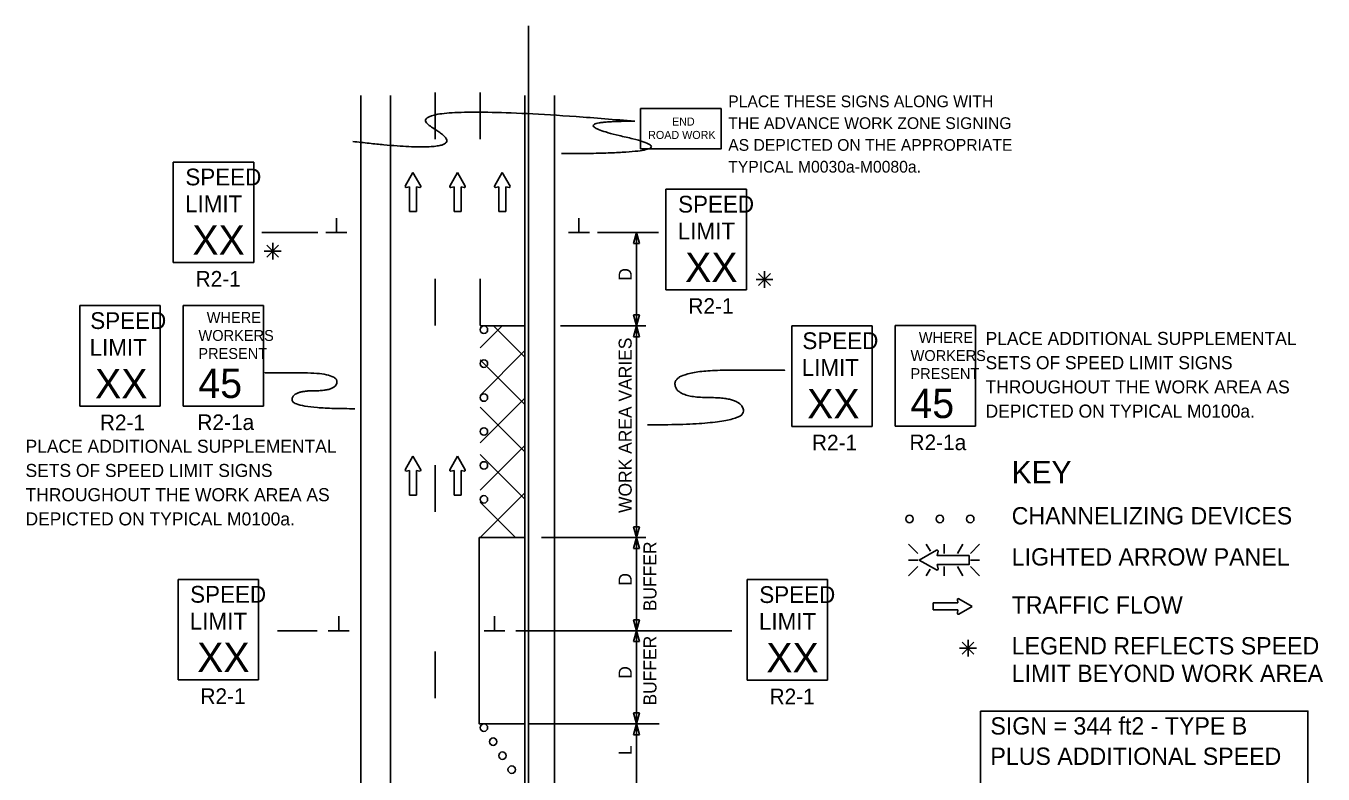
# Model space of a CAD drawing. Extents: x 16733 to 18475, y 5932 to 6964.
# Drawn here: x 16733 to 17429, y 6562 to 6964 of the extents above; entities that cross this region are included whole.
import ezdxf

# ---------------------------------------------------------------- set-up
doc = ezdxf.new("R2010")
doc.units = 0
for name, color, linetype in [('ALI_LEGAL_EX', 7, 'Continuous'), ('MT_SCRATCH_LEVEL_E', 7, 'Continuous'), ('PAVT_EDGE_EX', 7, 'Continuous'), ('TRAFFIC_SIGNS_PR', 7, 'Continuous'), ('TYPICAL_TEXT_DIMEN_EX', 7, 'Continuous'), ('TYPICAL_TEXT_DIMEN_PR', 7, 'Continuous')]:
    doc.layers.add(name, color=color, linetype=linetype)

msp = doc.modelspace()

# ---------------------------------------------------------------- linework, layer by layer
at = {"layer": 'ALI_LEGAL_EX'}
msp.add_line((17002.72, 6964.07), (17002.72, 6147.1), dxfattribs=at)
for points in [[(16952.72, 6928.28), (16952.72, 6903.28)], [(16976.72, 6928.28), (16976.72, 6903.28)], [(16952.72, 6828.28), (16952.72, 6803.28)], [(16976.72, 6828.28), (16976.72, 6803.28)], [(16952.72, 6728.28), (16952.72, 6703.28)], [(16952.72, 6628.28), (16952.72, 6603.28)]]:
    msp.add_lwpolyline(points, dxfattribs=at)
at = {"layer": 'MT_SCRATCH_LEVEL_E'}
for p, q in [((16940.72, 6885.31), (16936.61, 6878.07)), ((16944.87, 6878.07), (16940.72, 6885.31)), ((16964.62, 6885.31), (16960.51, 6878.07)), ((16968.77, 6878.07), (16964.62, 6885.31)), ((16988.68, 6885.31), (16984.56, 6878.07)), ((16992.82, 6878.07), (16988.68, 6885.31)), ((16937.09, 6877.38), (16938.87, 6877.7)), ((16938.87, 6877.7), (16938.87, 6864.44)), ((16942.61, 6864.44), (16942.61, 6877.7)), ((16942.61, 6877.7), (16944.39, 6877.38)), ((16960.99, 6877.38), (16962.77, 6877.7)), ((16962.77, 6877.7), (16962.77, 6864.44)), ((16966.51, 6864.44), (16966.51, 6877.7)), ((16966.51, 6877.7), (16968.29, 6877.38)), ((16985.05, 6877.38), (16986.82, 6877.7)), ((16986.82, 6877.7), (16986.82, 6864.44)), ((16990.57, 6864.44), (16990.57, 6877.7)), ((16990.57, 6877.7), (16992.34, 6877.38)), ((16938.87, 6864.44), (16942.61, 6864.44)), ((16962.77, 6864.44), (16966.51, 6864.44)), ((16986.82, 6864.44), (16990.57, 6864.44)), ((16940.72, 6733.05), (16936.61, 6725.81)), ((16944.87, 6725.81), (16940.72, 6733.05)), ((16964.62, 6733.05), (16960.51, 6725.81)), ((16968.77, 6725.81), (16964.62, 6733.05)), ((16937.09, 6725.13), (16938.87, 6725.44)), ((16938.87, 6725.44), (16938.87, 6712.19)), ((16942.61, 6712.19), (16942.61, 6725.44)), ((16942.61, 6725.44), (16944.39, 6725.13)), ((16960.99, 6725.13), (16962.77, 6725.44)), ((16962.77, 6725.44), (16962.77, 6712.19)), ((16966.51, 6712.19), (16966.51, 6725.44)), ((16966.51, 6725.44), (16968.29, 6725.13)), ((16938.87, 6712.19), (16942.61, 6712.19)), ((16962.77, 6712.19), (16966.51, 6712.19)), ((17233.37, 6654.33), (17220.11, 6654.33)), ((17220.11, 6654.33), (17220.11, 6650.59)), ((17233.05, 6656.11), (17233.37, 6654.33)), ((17240.98, 6652.48), (17233.74, 6656.59)), ((17233.74, 6648.33), (17240.98, 6652.48)), ((17220.11, 6650.59), (17233.37, 6650.59)), ((17233.37, 6650.59), (17233.05, 6648.81))]:
    msp.add_line(p, q, dxfattribs=at)
for centre, start, end in [((16937.02, 6877.84), 150.42484, 279.96381), ((16944.46, 6877.84), 260.03619, 29.77312), ((16960.92, 6877.84), 150.42484, 279.96381), ((16968.36, 6877.84), 260.03619, 29.77312), ((16984.97, 6877.84), 150.42484, 279.96381), ((16992.41, 6877.84), 260.03619, 29.77312), ((16937.02, 6725.59), 150.42484, 279.96381), ((16944.46, 6725.59), 260.03619, 29.77312), ((16960.92, 6725.59), 150.42484, 279.96381), ((16968.36, 6725.59), 260.03619, 29.77312), ((17233.51, 6656.18), 60.42484, 189.96381), ((17233.51, 6648.74), 170.03619, 299.77312)]:
    msp.add_arc(centre, 0.463, start, end, dxfattribs=at)
at = {"layer": 'PAVT_EDGE_EX'}
for p, q in [((16912.72, 6926.76), (16912.72, 6278.89)), ((16928.72, 6926.76), (16928.72, 6278.89)), ((17000.72, 6689.4), (17000.72, 6926.76)), ((17016.72, 6926.76), (17016.72, 6278.89)), ((17000.72, 6803.12), (16976.72, 6803.12)), ((16976.72, 6803.12), (17000.72, 6803.12)), ((16976.72, 6791.22), (16988.62, 6803.12)), ((17000.72, 6786.31), (16983.91, 6803.12)), ((16976.72, 6765.77), (17000.72, 6789.77)), ((17000.72, 6760.86), (16976.72, 6784.86)), ((16976.72, 6740.31), (17000.72, 6764.31)), ((17000.72, 6735.4), (16976.72, 6759.4)), ((16976.72, 6714.86), (17000.72, 6738.86)), ((17000.72, 6709.95), (16976.72, 6733.95)), ((16976.72, 6689.4), (17000.72, 6713.4)), ((16995.81, 6689.4), (16976.72, 6708.49)), ((17000.72, 6689.4), (17000.72, 6278.89))]:
    msp.add_line(p, q, dxfattribs=at)
msp.add_lwpolyline([(17000.72, 6689.4), (16976.34, 6689.4), (16976.34, 6589.4), (17000.72, 6589.4)], close=True, dxfattribs=at)
at = {"layer": 'TRAFFIC_SIGNS_PR'}
for p, q in [((16812.01, 6891.02), (16855.21, 6891.02)), ((16812.01, 6837.02), (16812.01, 6891.02)), ((16855.21, 6837.02), (16855.21, 6891.02)), ((17076.58, 6876.42), (17119.78, 6876.42)), ((17076.58, 6822.42), (17076.58, 6876.42)), ((17119.78, 6822.42), (17119.78, 6876.42)), ((16812.01, 6837.02), (16855.21, 6837.02)), ((17076.58, 6822.42), (17119.78, 6822.42)), ((16761.78, 6813.92), (16804.98, 6813.92)), ((16761.78, 6759.92), (16761.78, 6813.92)), ((16804.98, 6759.92), (16804.98, 6813.92)), ((16817.24, 6814.02), (16860.44, 6814.02)), ((16817.24, 6760.02), (16817.24, 6814.02)), ((16860.44, 6760.02), (16860.44, 6814.02)), ((17144.14, 6803.12), (17187.34, 6803.12)), ((17144.14, 6749.12), (17144.14, 6803.12)), ((17187.34, 6749.12), (17187.34, 6803.12)), ((17199.61, 6803.22), (17242.81, 6803.22)), ((17199.61, 6749.22), (17199.61, 6803.22)), ((17242.81, 6749.22), (17242.81, 6803.22)), ((16761.78, 6759.92), (16804.98, 6759.92)), ((16817.24, 6760.02), (16860.44, 6760.02)), ((17144.14, 6749.12), (17187.34, 6749.12)), ((17199.61, 6749.22), (17242.81, 6749.22)), ((17206.79, 6685.86), (17211.72, 6680.93)), ((17218.55, 6682.04), (17216.34, 6685.86)), ((17225.87, 6680.93), (17225.87, 6685.86)), ((17233.11, 6680.93), (17235.96, 6685.86)), ((17240.02, 6680.93), (17244.96, 6685.87)), ((17211.72, 6677.37), (17206.79, 6677.37)), ((17206.79, 6668.89), (17211.72, 6673.82)), ((17216.3, 6668.88), (17218.41, 6672.54)), ((17225.87, 6673.82), (17225.87, 6668.88)), ((17236, 6668.88), (17233.15, 6673.82)), ((17240.02, 6677.37), (17244.96, 6677.37)), ((17240.02, 6673.82), (17244.96, 6668.88)), ((16814.57, 6666.98), (16857.77, 6666.98)), ((16814.57, 6612.98), (16814.57, 6666.98)), ((16857.77, 6612.98), (16857.77, 6666.98)), ((17120.18, 6666.82), (17163.38, 6666.82)), ((17120.18, 6612.82), (17120.18, 6666.82)), ((17163.38, 6612.82), (17163.38, 6666.82)), ((16814.57, 6612.98), (16857.77, 6612.98)), ((17120.18, 6612.82), (17163.38, 6612.82))]:
    msp.add_line(p, q, dxfattribs=at)
msp.add_lwpolyline([(17062.94, 6898.07), (17106.14, 6898.07), (17106.14, 6919.67), (17062.94, 6919.67)], close=True, dxfattribs=at)
msp.add_lwpolyline([(17062.94, 6898.07), (17106.14, 6898.07), (17106.14, 6919.67), (17062.94, 6919.67)], close=True, dxfattribs=at)
for points in [[(17221.8, 6682.65), (17212.51, 6677.37), (17221.8, 6672.05)], [(17222.67, 6672.68), (17222.27, 6674.95), (17239.29, 6674.95), (17239.29, 6679.75), (17222.27, 6679.75), (17222.68, 6682.03)]]:
    msp.add_lwpolyline(points, dxfattribs=at)
for centre in [(16978.82, 6801), (16978.82, 6782.79), (16978.82, 6764.57), (16978.82, 6746.36), (16978.82, 6728.15), (16978.82, 6709.93), (17207.35, 6699.41), (17223.65, 6699.41), (17239.95, 6699.41), (16978.82, 6587.35), (16983.79, 6579.84), (16988.76, 6572.33), (16993.73, 6564.83)]:
    msp.add_circle(centre, 2, dxfattribs=at)
for centre, radius, start, end in [((17222.09, 6682.13), 0.598, 350.73078, 118.89165), ((17222.09, 6672.58), 0.597, 241.48329, 9.95933)]:
    msp.add_arc(centre, radius, start, end, dxfattribs=at)
for points in [[(16908.42, 6902.07), (16977.88, 6893.76), (16925.65, 6924.32), (17059.88, 6912.94)], [(17059.88, 6912.94), (17017.37, 6912.94), (17093.89, 6895.53), (17020.55, 6895.53)]]:
    msp.add_open_spline(points, degree=2, dxfattribs=at)
at = {"layer": 'TYPICAL_TEXT_DIMEN_EX'}
msp.add_lwpolyline([(17245.38, 6596.3), (17421.3, 6596.3), (17421.3, 6530.87), (17245.38, 6530.87)], close=True, dxfattribs=at)
at = {"layer": 'TYPICAL_TEXT_DIMEN_PR'}
for p, q in [((16899.6, 6853.12), (16899.6, 6860.91)), ((17029.85, 6853.12), (17029.85, 6860.91)), ((16859.58, 6853.12), (16889.72, 6853.12)), ((16865.4, 6843.18), (16865.4, 6847.63)), ((16893.97, 6853.12), (16905.22, 6853.12)), ((17035.47, 6853.12), (17024.22, 6853.12)), ((17072.51, 6853.12), (17039.72, 6853.12)), ((17059.15, 6847.26), (17060.72, 6853.12)), ((17060.72, 6847.26), (17059.15, 6847.26)), ((17060.72, 6853.12), (17062.29, 6847.26)), ((17060.72, 6853.12), (17060.72, 6803.12)), ((17062.29, 6847.26), (17060.72, 6847.26)), ((16865.4, 6843.18), (16860.87, 6843.18)), ((16862.22, 6846.37), (16868.59, 6839.99)), ((16868.59, 6846.37), (16862.22, 6839.99)), ((16865.4, 6843.18), (16868.59, 6843.18)), ((16865.4, 6843.18), (16869.88, 6843.18)), ((16865.4, 6843.18), (16865.4, 6838.68)), ((17129.48, 6827.99), (17124.95, 6827.99)), ((17126.3, 6831.18), (17132.67, 6824.8)), ((17132.67, 6831.18), (17126.3, 6824.8)), ((17129.48, 6827.99), (17129.48, 6832.44)), ((17129.48, 6827.99), (17132.67, 6827.99)), ((17129.48, 6827.99), (17133.96, 6827.99)), ((17129.48, 6827.99), (17129.48, 6823.49)), ((17060.72, 6803.12), (17059.15, 6808.99)), ((17059.15, 6808.99), (17060.72, 6808.99)), ((17060.72, 6808.99), (17062.29, 6808.99)), ((17062.29, 6808.99), (17060.72, 6803.12)), ((17065.72, 6803.12), (17020.02, 6803.12)), ((17059.15, 6797.26), (17060.72, 6803.12)), ((17060.72, 6689.4), (17060.72, 6803.12)), ((17060.72, 6803.12), (17062.29, 6797.26)), ((17060.72, 6797.26), (17059.15, 6797.26)), ((17062.29, 6797.26), (17060.72, 6797.26)), ((17060.72, 6689.4), (17059.15, 6695.26)), ((17059.15, 6695.26), (17060.72, 6695.26)), ((17060.72, 6695.26), (17062.29, 6695.26)), ((17062.29, 6695.26), (17060.72, 6689.4)), ((17065.72, 6689.4), (17009.81, 6689.4)), ((17059.15, 6683.54), (17060.72, 6689.4)), ((17060.72, 6689.4), (17060.72, 6639.4)), ((17060.72, 6689.4), (17062.29, 6683.54)), ((17060.72, 6683.54), (17059.15, 6683.54)), ((17062.29, 6683.54), (17060.72, 6683.54)), ((16900.88, 6639.4), (16900.88, 6647.18)), ((16984.5, 6639.4), (16984.5, 6647.18)), ((17060.72, 6639.4), (17059.15, 6645.26)), ((17059.15, 6645.26), (17060.72, 6645.26)), ((17060.72, 6645.26), (17062.29, 6645.26)), ((17062.29, 6645.26), (17060.72, 6639.4)), ((16889.26, 6639.4), (16867.89, 6639.4)), ((16906.5, 6639.4), (16895.25, 6639.4)), ((16990.12, 6639.4), (16978.87, 6639.4)), ((17111.87, 6639.4), (16995.92, 6639.4)), ((17059.15, 6633.54), (17060.72, 6639.4)), ((17060.72, 6639.4), (17060.72, 6589.4)), ((17060.72, 6639.4), (17062.29, 6633.54)), ((17060.72, 6633.54), (17059.15, 6633.54)), ((17062.29, 6633.54), (17060.72, 6633.54)), ((17235.58, 6633.2), (17241.95, 6626.83)), ((17241.95, 6633.2), (17235.58, 6626.83)), ((17238.76, 6630.01), (17238.76, 6634.47)), ((17238.76, 6630.01), (17234.23, 6630.01)), ((17238.76, 6630.01), (17241.95, 6630.01)), ((17238.76, 6630.01), (17243.24, 6630.01)), ((17238.76, 6630.01), (17238.76, 6625.51)), ((17072.94, 6589.4), (17002.54, 6589.4)), ((17060.72, 6589.4), (17059.15, 6595.26)), ((17059.15, 6595.26), (17060.72, 6595.26)), ((17059.15, 6583.54), (17060.72, 6589.4)), ((17060.72, 6595.26), (17062.29, 6595.26)), ((17062.29, 6595.26), (17060.72, 6589.4)), ((17060.72, 6555.21), (17060.72, 6589.4)), ((17060.72, 6589.4), (17062.29, 6583.54)), ((17060.72, 6583.54), (17059.15, 6583.54)), ((17062.29, 6583.54), (17060.72, 6583.54))]:
    msp.add_line(p, q, dxfattribs=at)
for points in [[(16909.54, 6758.58), (16875.78, 6758.58), (16875.78, 6768.22), (16899.89, 6768.22), (16899.89, 6777.86), (16861.31, 6777.86), (16861.31, 6777.86)], [(17066.7, 6749.88), (17118.15, 6749.88), (17118.15, 6764.58), (17081.4, 6764.58), (17081.4, 6779.28), (17140.2, 6779.28), (17140.2, 6779.28)]]:
    msp.add_open_spline(points, degree=2, dxfattribs=at)

# ---------------------------------------------------------------- texts
at = {"layer": 'TRAFFIC_SIGNS_PR'}
for s, height, p in [('PLACE THESE SIGNS ALONG WITH', 6.3, (17110, 6920.44)), ('END', 4.31, (17079.82, 6910.59)), ('END', 4.31, (17079.82, 6910.59)), ('THE ADVANCE WORK ZONE SIGNING', 6.3, (17110, 6908.74)), ('ROAD WORK', 4.31, (17067, 6903.41)), ('ROAD WORK', 4.31, (17067, 6903.4)), ('AS DEPICTED ON THE APPROPRIATE', 6.3, (17110, 6897.04)), ('TYPICAL M0030a-M0080a.', 6.3, (17110, 6885.34)), ('SPEED', 9, (16818.5, 6878.49)), ('LIMIT', 9, (16818.31, 6864.09)), ('SPEED', 9, (17083.07, 6863.89)), ('XX', 15.785, (16822.26, 6841.24)), ('LIMIT', 9, (17082.89, 6849.49)), ('XX', 15.785, (17086.83, 6826.64)), ('R2-1', 8.37, (16824.02, 6824.15)), ('R2-1', 8.37, (17088.59, 6809.55)), ('SPEED', 9, (16767.44, 6801.39)), ('WHERE', 5.85, (16829.97, 6804.66)), ('WORKERS', 5.85, (16825.55, 6794.99)), ('SPEED', 9, (17149.81, 6790.59)), ('WHERE', 5.85, (17212.33, 6793.87)), ('PLACE ADDITIONAL SUPPLEMENTAL', 7, (17248.18, 6792.81)), ('LIMIT', 9, (16767.07, 6786.99)), ('PRESENT', 5.85, (16825.47, 6785.31)), ('LIMIT', 9, (17149.43, 6776.19)), ('WORKERS', 5.85, (17207.91, 6784.19)), ('SETS OF SPEED LIMIT SIGNS', 7, (17248.18, 6779.81)), ('XX', 15.785, (16770, 6764.15)), ('45', 15.785, (16825.46, 6764.35)), ('PRESENT', 5.85, (17207.84, 6774.52)), ('THROUGHOUT THE WORK AREA AS', 7, (17248.18, 6766.81)), ('XX', 15.785, (17152.36, 6753.35)), ('45', 15.785, (17207.83, 6753.56)), ('DEPICTED ON TYPICAL M0100a.', 7, (17248.18, 6753.81)), ('R2-1', 8.37, (16772.59, 6747.05)), ('R2-1a', 8.37, (16824.95, 6747.15)), ('PLACE ADDITIONAL SUPPLEMENTAL', 7, (16732.69, 6734.94)), ('R2-1', 8.37, (17154.95, 6736.25)), ('R2-1a', 8.37, (17207.32, 6736.35)), ('SETS OF SPEED LIMIT SIGNS', 7, (16732.69, 6721.94)), ('THROUGHOUT THE WORK AREA AS', 7, (16732.69, 6708.94)), ('DEPICTED ON TYPICAL M0100a.', 7, (16732.69, 6695.94)), ('SPEED', 9, (16821.06, 6654.45)), ('SPEED', 9, (17126.67, 6654.29)), ('LIMIT', 9, (16820.87, 6640.05)), ('LIMIT', 9, (17126.49, 6639.89)), ('XX', 15.785, (16824.82, 6617.21)), ('XX', 15.785, (17130.44, 6617.05)), ('R2-1', 8.37, (16826.58, 6600.11)), ('R2-1', 8.37, (17132.19, 6599.95))]:
    msp.add_text(s, height=height, dxfattribs=at).set_placement(p)
at = {"layer": 'TYPICAL_TEXT_DIMEN_EX'}
for s, height, p in [('KEY', 12, (17262.19, 6718.51)), ('CHANNELIZING DEVICES', 9.3, (17262.19, 6696.46)), ('LIGHTED ARROW PANEL', 9.3, (17262.19, 6674.41)), ('TRAFFIC FLOW', 9.3, (17262.19, 6648.61)), ('LEGEND REFLECTS SPEED', 9.3, (17262.19, 6626.66)), ('LIMIT BEYOND WORK AREA', 9.3, (17262.19, 6611.86)), ('SIGN = 344 ft2 - TYPE B', 9.3, (17250.77, 6583.67)), ('PLUS ADDITIONAL SPEED', 9.3, (17250.77, 6567.37))]:
    msp.add_text(s, height=height, dxfattribs=at).set_placement(p)
at = {"layer": 'TYPICAL_TEXT_DIMEN_PR'}
for s, p in [('D', (17058.16, 6827.34)), ('WORK AREA VARIES', (17058.16, 6702.62)), ('BUFFER', (17071.48, 6649.89)), ('D', (17058.16, 6663.62)), ('BUFFER', (17071.48, 6599.26)), ('D', (17058.16, 6613.62)), ('L', (17058.16, 6572.69))]:
    msp.add_text(s, height=7, rotation=90, dxfattribs=at).set_placement(p)

doc.saveas('drawing.dxf')
